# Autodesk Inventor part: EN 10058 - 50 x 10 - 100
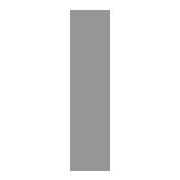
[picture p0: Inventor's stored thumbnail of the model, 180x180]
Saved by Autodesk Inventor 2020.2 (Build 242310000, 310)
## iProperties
Created: 2019-01
Part Number: EN 10058 - 50 x 10 - 100
Material: Stahl, weich
Description: Warmgewalzte Flachstahlprofile - Mehrzweck
Document SubType Name: Modeling
Standard: DIN
Designer: lutzd
Standard Revision: 2004
Standards Organization: DIN
Language: de-DE
Size Designation: 50 x 10
Categories: <MemberInstance><Categories><Category DisplayName="Profile" InternalName="089c4875-fa83-4c05-b084-43b9cc11f5ed" Mnemonic="GRDR"><CategoryParameter DisplayName="
Stock Number: 50 x 10
Mass: 387.052 g
Surface Area: 132.788 cm^2
Volume: 49.306 cm^3
Density: 7.85 g/cm^3
Appearance: Semi-Polished(8)
_CCFamilyMember: 59
_CCFamilyDisplayName: DIN EN 10058 - Warmgewalzte Flachstahlprofile - Mehrzweck
_FrameMemberDoc: Frame Member File
_Version: 15.0.0
_GetPNFromCC: 1
IsCustomPart: 1
G_L: 100,000 mm
G_W: 10,000 mm
G_H: 50,000 mm
DocNumber: ADSK-014432
Folder: .
Mass: 0,387 kg
VLT_Material: Stahl, weich
Dimensions: 50x10x100 mm
Title: Profil-Bauteil
Author: lutzd
Revision Number: -
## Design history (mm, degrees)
node "Startebene"
node "Endebene"
sketch "Skizze"
  geometry: L1 (5, -25)-(-5, -25); L2 (-5, -25)-(-5, 25); L3 (-5, 25)-(5, 25); L4 (5, 25)-(5, -25); L5 (-6, 0)-(8, 0); L6 (0, -30)-(0, 40); L7 (0, 54)-(0, -44) reference; L8 (-9.2, 0)-(13.2, 0) reference
  constraints: 12 end point, 2 collinear, 2 parallel, 1 horizontal, 1 perpendicular
  dimensions: "d0" = 50 distance between parallel lines of L3 L1 (= G_W); "d1" = 10 distance between parallel lines of L4 L2 (= G_H); "d4" = 5 distance between parallel lines of L6 L4 (= 0.5 x d1); "d5" = 25 distance between parallel lines of L5 L3 (= 0.5 x d0)
extrude "Körper" new body sketch "Skizze" stored distance "d2" = 100 (= G_L); taper "d3" = 0 deg
node "Driven Length"
  sketch "Sketch3"
    geometry: L1 (0, 0)-(10, 0) reference
    constraints: 2 end point, 1 horizontal
  workplane "Work Plane3"
  sketch "Sketch4"
    geometry: L1 (-2, 0)-(12, 0) reference; L2 (-2, 100)-(12, 100) reference
    dimensions: "d9" = 100 distance between parallel lines of L1 L2 (derived)
sketch "Skizze5"
  geometry: L1 (16, 25)-(84, 25); L2 (100, 50)-(0, 50) reference; L3 (100, 50)-(100, 0) reference; 6 further points
  constraints: 3 midpoint, 2 coincident, 2 end point, 1 horizontal, 1 horizontal alignment, 1 vertical alignment
  dimensions: "d10" = 68 distance of L1.start L1.end
hole "Bohrung1" sketch "Skizze5" at (16, 25), (84, 25) diameter "d11" = 6.647; stored, may be unused: countersink angle "d15" = 90 deg, drill point angle "d17" = 118 deg; dims "d12" = 16, "d13" = 4, "d14" = 2, "d16" = 8
body "Solid1"
other parameters: "G_W" = 50 [user parameter; used in 1 equation term], "G_H" = 10 [user parameter; used in 1 equation term], "G_L" = 100 (= d9) [user parameter; used in 1 equation term], "G_OFFSET_START" = 0 [user parameter; used in 1 equation term], "G_OFFSET_END" = 0 [user parameter; used in 1 equation term], "d6" = 0 (computed from G_OFFSET_START), "d8" = 90 deg, "MAS" = 0.393 [user parameter]
